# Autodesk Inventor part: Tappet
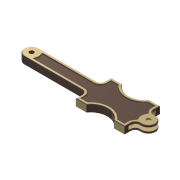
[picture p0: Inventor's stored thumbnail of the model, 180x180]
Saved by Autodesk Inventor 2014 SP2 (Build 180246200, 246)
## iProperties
Created: 2016-02
Part Number: Tappet
Material: Steel
Document SubType Name: Modeling
Designer: User
Density: 7.85 g/cm^3
Appearance: Gunmetal - Antique Polished
Author: User
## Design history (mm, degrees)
sketch "Sketch1"
  geometry: L1 (27.5, -20)-(15.5, -20); L2 (-27.5, -20)-(-27.5, -13); L3 (-27.5, 20)-(-15.5, 20); L4 (27.5, 20)-(27.5, 13); L5 (27.5, -20)-(-27.5, 20); L6 (-27.5, -20)-(27.5, 20); L7 (15.5, 20)-(27.5, 20); L8 (-15.5, 20)-(15.5, 20); L9 (15.5, -20)-(-15.5, -20); L10 (-15.5, -20)-(-27.5, -20); L11 (-32.5, 8)-(-97.5, 8); L12 (-97.5, -8)-(-32.5, -8); L13 (-27.5, 13)-(-27.5, 20); L14 (-27.5, -8)-(-27.5, 8); L15 (32.5, 8)-(34.5, 8); L16 (34.5, -8)-(32.5, -8); L17 (27.5, 8)-(27.5, -8); L18 (27.5, -13)-(27.5, -20); A1 r 19 centre (0, 30.989) between (-15.5, 20) and (15.5, 20); A2 r 19 centre (0, -30.989) between (15.5, -20) and (-15.5, -20); A3 r 8 centre (-97.5, 0) between (-97.5, 8) and (-97.5, -8); A4 r 8 centre (34.5, 0) between (34.5, -8) and (34.5, 8); A5 r 5 centre (-32.5, 13) between (-32.5, 8) and (-27.5, 13); A6 r 5 centre (-32.5, -13) between (-27.5, -13) and (-32.5, -8); A7 r 5 centre (32.5, 13) between (27.5, 13) and (32.5, 8); A8 r 5 centre (32.5, -13) between (32.5, -8) and (27.5, -13); 4 further points
  constraints: 36 end point, 18 parallel, 16 perpendicular, 16 point on circle, 12 tangent, 10 point on line, 8 centre point, 4 equal radius, 4 horizontal, 4 midpoint, 3 vertical alignment, 2 horizontal alignment, 1 coincident, 1 collinear
  dimensions: "d0" = 55 distance of L3.start L4.start; "d1" = 40 distance of L2.start L3.start; "d2" = 19 radius of A1; "d4" = 12 distance of L3.start L3.end; "d5" = 16 distance between parallel lines of L12 L11; "d6" = 70 distance from line of L2 A3.centre; "d7" = 132 distance of A4.centre A3.centre; "d8" = 5 radius of A5
extrude "Extrusion1" new body sketch "Sketch1" stored distance "d9" = 8; taper "d10" = 0 deg
sketch "Sketch2"
  geometry: A1 r 8 centre (-97.5, 0) between (-97.5, 8) and (-97.5, -8) reference; 2 further points
hole "Hole1" sketch "Sketch2" at (-97.5, 0), (34.5, 0) diameter "d11" = 5; stored, may be unused: countersink angle "d15" = 90 deg, drill point angle "d17" = 118 deg; dims "d12" = 6, "d13" = 4, "d14" = 2, "d16" = 8
sketch "Sketch3"
  geometry: L1 (15.5, -20)-(27.5, -20) reference; L2 (27.5, -20)-(27.5, -13) reference; L3 (27.5, 13)-(27.5, 20) reference; L4 (27.5, 20)-(15.5, 20) reference; L5 (-15.5, 20)-(-27.5, 20) reference; L6 (-27.5, 20)-(-27.5, 13) reference; L7 (-32.5, 8)-(-97.5, 8) reference; L8 (-27.5, -13)-(-27.5, -20) reference; L9 (-27.5, -20)-(-15.5, -20) reference; L10 (-91.691, 5.5)-(-32.5, 5.5); L11 (-25, 13)-(-25, 17.5); L12 (-25, 17.5)-(-16.742, 17.5); L13 (16.742, 17.5)-(25, 17.5); L14 (25, 17.5)-(25, 13); L15 (25, -13)-(25, -17.5); L16 (25, -17.5)-(16.742, -17.5); L17 (-16.742, -17.5)-(-25, -17.5); L18 (-25, -17.5)-(-25, -13); L19 (-32.5, -5.5)-(-91.691, -5.5); A1 r 5 centre (32.5, -13) between (32.5, -8) and (27.5, -13) reference; A2 r 8 centre (34.5, 0) between (34.5, -8) and (34.5, 8) reference; A3 r 5 centre (32.5, 13) between (27.5, 13) and (32.5, 8) reference; A4 r 19 centre (0, 30.989) between (-15.5, 20) and (15.5, 20) reference; A5 r 5 centre (-32.5, 13) between (-32.5, 8) and (-27.5, 13) reference; A6 r 8 centre (-97.5, 0) between (-97.5, 8) and (-97.5, -8) reference; A7 r 5 centre (-32.5, -13) between (-27.5, -13) and (-32.5, -8) reference; A8 r 19 centre (0, -30.989) between (15.5, -20) and (-15.5, -20) reference; A9 r 7.5 centre (-32.5, 13) between (-32.5, 5.5) and (-25, 13); A10 r 21.5 centre (0, 30.989) between (-16.742, 17.5) and (16.742, 17.5); A11 r 7.5 centre (32.5, 13) between (25, 13) and (27.632, 7.294); A12 r 7.5 centre (32.5, -13) between (27.632, -7.294) and (25, -13); A13 r 21.5 centre (0, -30.989) between (16.742, -17.5) and (-16.742, -17.5); A14 r 7.5 centre (-32.5, -13) between (-25, -13) and (-32.5, -5.5); A15 r 8 centre (-97.5, 0) between (-91.691, -5.5) and (-91.691, 5.5); A16 r 8 centre (34.5, 0) between (27.968, 4.618) and (27.968, -4.618); A17 r 2 centre (26.334, 5.773) between (27.968, 4.618) and (27.632, 7.294); A18 r 2 centre (26.334, -5.773) between (27.632, -7.294) and (27.968, -4.618); 1 further point
  constraints: 20 end point, 20 point on circle, 10 centre point, 4 tangent, 3 equal radius, 2 coincident, 11 other
  dimensions: "d19" = 2.5 distance between parallel lines of L7 L10; "d24" = 4 diameter of A17
extrude "Extrusion2" cut sketch "Sketch3" distance "d21" = 1; taper "d22" = 0 deg
fillet "Fillet1" dims "d23" = 1
fillet "Fillet2" dims "d25" = 1
chamfer "Chamfer1" distance "d30" = 0.5; stored, may be unused: second distance "d31" = 2, angle "d32" = 45 deg
mirror "Mirror1"
sketch "Sketch4"
  geometry: C1 r 36 at (60, 0); 1 further point
  constraints: 1 centre point, 1 horizontal alignment
  dimensions: "d26" = 60 distance of C1.centre point (0, 0); "d27" = 72 diameter of C1
extrude "Extrusion3" cut sketch "Sketch4" stored distance "d28" = 4; taper "d29" = 0 deg
chamfer "Chamfer2" distance "d33" = 0.5; stored, may be unused: second distance "d34" = 2, angle "d35" = 45 deg
body "Solid1"
